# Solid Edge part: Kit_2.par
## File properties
Sűrűség: 0,000 kg/m^3
Pontosság: 0,990
Author: bmolnar
Last saved by: bmolnar
Revision: 77
Username: bmolnar
Dokumentum tartalom típus: 0
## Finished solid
Body 1: solid body, 13 faces, 18 edges, 14 vertices, 2 separate solids.
  Faces by surface: plane 7, cylinder 4, cone 1, torus 1
  Edges by curve: circle 10, line 8
Bounding box of the edges (mm; curved faces can reach further): 19.000 x 18.450 x 3.100, from (-9.5, -9.5, 0.3) to (9.5, 8.95, 3.4).
Cylindrical faces by radius (mm): R7 x1, R8.5 x1, R8.95 x1, R9.5 x1
Conical faces (half-angle, radius in mm at the cone's reference point): 45 deg R6.75 x1
Toroidal faces (ring radius, tube radius in mm): R7.4 r0.4 x1
Planar faces by outward normal: +z 2, -z 3, oblique 2
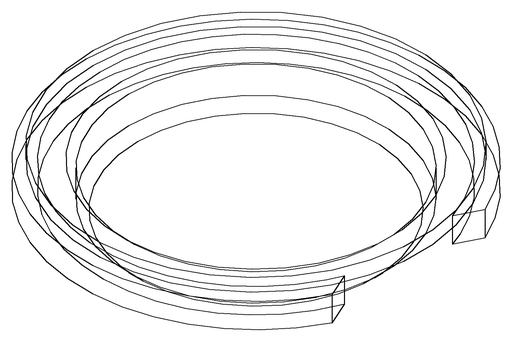
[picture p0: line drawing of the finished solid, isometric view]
